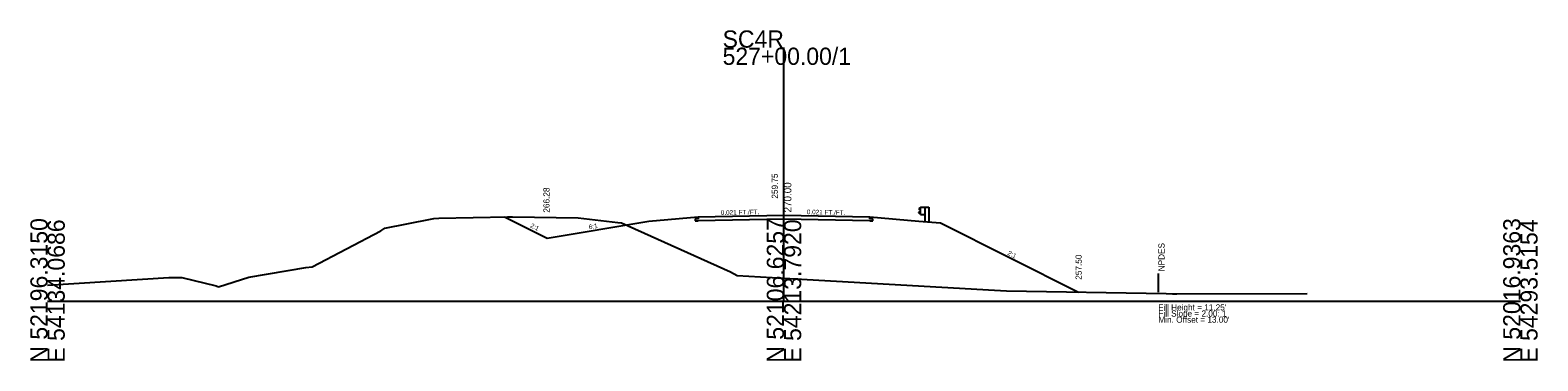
# Model space of a CAD drawing. Extents: x 9740 to 17409, y 8856 to 28416.
# Drawn here: x 10763 to 11008.7, y 27861.7 to 27915.5 of the extents above; entities that cross this region are included whole.
import ezdxf

# ---------------------------------------------------------------- set-up
doc = ezdxf.new("R2010")
doc.units = 0
for name, color, linetype in [('Level 10', 7, 'Continuous'), ('Level 11', 7, 'Continuous'), ('Level 12', 7, 'Continuous'), ('Level 24', 7, 'Continuous'), ('Level 32', 7, 'Continuous'), ('Level 33', 7, 'Continuous'), ('Level 50', 7, 'Continuous'), ('Level 55', 7, 'Continuous'), ('Level 59', 7, 'Continuous'), ('Level 6', 7, 'Continuous'), ('Level 60', 7, 'Continuous'), ('Level 63', 7, 'Continuous'), ('Level 7', 7, 'Continuous')]:
    doc.layers.add(name, color=color, linetype=linetype)

msp = doc.modelspace()

# ---------------------------------------------------------------- linework, layer by layer
at = {"layer": 'Level 11'}
for p, q in [((10871.85, 27885.09), (10871.85, 27884.79)), ((10899.85, 27884.79), (10899.85, 27885.09)), ((10871.85, 27884.79), (10871.35, 27884.78)), ((10871.35, 27884.78), (10871.35, 27884.44)), ((10871.35, 27884.44), (10871.85, 27884.45)), ((10900.35, 27884.78), (10899.85, 27884.79)), ((10899.85, 27884.45), (10900.35, 27884.44)), ((10900.35, 27884.44), (10900.35, 27884.78))]:
    msp.add_line(p, q, dxfattribs=at)
at = {"layer": 'Level 12'}
for p, q in [((10885.85, 27884.74), (10871.85, 27884.45)), ((10899.85, 27884.45), (10885.85, 27884.74))]:
    msp.add_line(p, q, dxfattribs=at)
at = {"layer": 'Level 24'}
for p, q in [((10908.12, 27886.6), (10907.85, 27886.4)), ((10907.85, 27886.4), (10907.85, 27886.35)), ((10907.85, 27886.35), (10908.12, 27886.15)), ((10907.85, 27885.83), (10908.12, 27886.03)), ((10907.85, 27885.78), (10907.85, 27885.83)), ((10908.12, 27885.58), (10907.85, 27885.78)), ((10908.12, 27885.51), (10908.12, 27886.67)), ((10908.12, 27886.67), (10908.79, 27886.67)), ((10908.12, 27885.51), (10908.79, 27885.51)), ((10908.79, 27886.67), (10908.79, 27884.34)), ((10908.79, 27886.67), (10909.46, 27886.67)), ((10909.46, 27886.67), (10909.46, 27884.29))]:
    msp.add_line(p, q, dxfattribs=at)
at = {"layer": 'Level 55'}
msp.add_line((10946.86, 27872.88), (10946.86, 27875.88), dxfattribs=at)
at = {"layer": 'Level 59'}
for p, q in [((10871.85, 27885.09), (10885.85, 27885.38)), ((10885.85, 27885.38), (10899.85, 27885.09))]:
    msp.add_line(p, q, dxfattribs=at)
at = {"layer": 'Level 6'}
for p, q in [((10863.85, 27884.42), (10871.85, 27885.09)), ((10899.85, 27885.09), (10907.85, 27884.42)), ((10907.85, 27884.42), (10911.35, 27884.13))]:
    msp.add_line(p, q, dxfattribs=at)
at = {"layer": 'Level 60'}
for p, q in [((10828.24, 27884.75), (10828.78, 27884.86)), ((10828.78, 27884.86), (10829.62, 27884.88)), ((10829.62, 27884.88), (10840.78, 27885.14)), ((10840.78, 27885.14), (10841.62, 27885.12)), ((10841.62, 27885.12), (10852.29, 27884.94)), ((10852.29, 27884.94), (10858.76, 27884.21)), ((10808.99, 27876.99), (10820.16, 27882.85)), ((10820.16, 27882.85), (10820.79, 27883.29)), ((10820.79, 27883.29), (10828.24, 27884.75)), ((10858.76, 27884.21), (10859.36, 27884.13)), ((10859.36, 27884.13), (10877.16, 27876.16)), ((10765.85, 27873.99), (10785.59, 27875.22)), ((10785.59, 27875.22), (10787.72, 27875.27)), ((10787.72, 27875.27), (10793.31, 27873.87)), ((10793.72, 27873.74), (10798.65, 27875.29)), ((10798.65, 27875.29), (10807.96, 27876.87)), ((10807.96, 27876.87), (10808.99, 27876.99)), ((10877.16, 27876.16), (10878.21, 27875.56)), ((10878.21, 27875.56), (10885.85, 27875.13)), ((10885.85, 27875.13), (10920.16, 27873.2)), ((10793.31, 27873.87), (10793.72, 27873.74)), ((10920.16, 27873.2), (10922.13, 27873.09)), ((10922.13, 27873.09), (10948.15, 27872.62)), ((10948.15, 27872.62), (10949.16, 27872.61)), ((10949.16, 27872.61), (10949.89, 27872.61)), ((10949.89, 27872.61), (10971.09, 27872.63))]:
    msp.add_line(p, q, dxfattribs=at)
at = {"layer": 'Level 63'}
for p, q in [((10885.85, 27871.38), (10885.85, 27912.65)), ((10765.85, 27871.38), (10885.85, 27871.38)), ((10885.85, 27871.38), (11005.85, 27871.38))]:
    msp.add_line(p, q, dxfattribs=at)
at = {"layer": 'Level 7'}
for p, q in [((10840.31, 27885.13), (10847.25, 27881.66)), ((10847.25, 27881.66), (10863.85, 27884.42)), ((10911.35, 27884.13), (10933.86, 27872.88))]:
    msp.add_line(p, q, dxfattribs=at)

# ---------------------------------------------------------------- texts
at = {"layer": 'Level 10'}
msp.add_text('259.75', height=1, rotation=90, dxfattribs=at).set_placement((10884.85, 27888.08))
at = {"layer": 'Level 32'}
for s, rotation, p in [('0.021 FT./FT.', 1.1916, (10875.56, 27885.42)), ('0.021 FT./FT.', 358.8084, (10889.57, 27885.55)), ('2:1', 333.435, (10844.43, 27883.45)), ('6:1', 9.4623, (10854.11, 27883.08)), ('2:1', 333.435, (10922.21, 27878.98))]:
    msp.add_text(s, height=0.75, rotation=rotation, dxfattribs=at).set_placement(p)
at = {"layer": 'Level 33'}
for s, p in [('266.28', (10847.64, 27885.8)), ('257.50', (10934.36, 27874.88))]:
    msp.add_text(s, height=1, rotation=90, dxfattribs=at).set_placement(p)
at = {"layer": 'Level 50'}
msp.add_text(' NPDES', height=1, rotation=90, dxfattribs=at).set_placement((10947.86, 27875.88))
for s, p in [("Fill Height = 11.25' ", (10946.86, 27869.88)), ('Fill Slope = 2.00: 1', (10946.86, 27868.88)), ("Min. Offset = 13.00' ", (10946.86, 27867.88))]:
    msp.add_text(s, height=1, dxfattribs=at).set_placement(p)
at = {"layer": 'Level 59'}
msp.add_text(' 270.00', height=1.2, rotation=90, dxfattribs=at).set_placement((10887.05, 27885.38))
at = {"layer": 'Level 63'}
for s, p in [('SC4R', (10875.85, 27912.65)), ('527+00.00/1', (10875.85, 27909.85))]:
    msp.add_text(s, height=2.8, dxfattribs=at).set_placement(p)
for s, p in [('N 52196.3150', (10765.85, 27861.38)), ('E 54134.0686', (10768.65, 27861.38)), ('N 52106.6257', (10885.85, 27861.38)), ('E 54213.7920', (10888.65, 27861.38)), ('N 52016.9363', (11005.85, 27861.38)), ('E 54293.5154', (11008.65, 27861.38))]:
    msp.add_text(s, height=2.8, rotation=90, dxfattribs=at).set_placement(p)

doc.saveas('drawing.dxf')
